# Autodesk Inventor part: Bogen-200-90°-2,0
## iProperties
Created: 2012-04
Part Number: Bogen-200-90°-2,0
Document SubType Name: Modeling
Designer: T.Cybinski
Mass: 361.232 g
Surface Area: 9040.8 cm^2
Volume: 361.232 cm^3
Density: 1 g/cm^3
Author: T.Cybinski
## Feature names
1. Umdrehung1 [Revolution]
2. Umdrehung4 [Revolution]
3. Sweeping2
4. Wandstärke2
